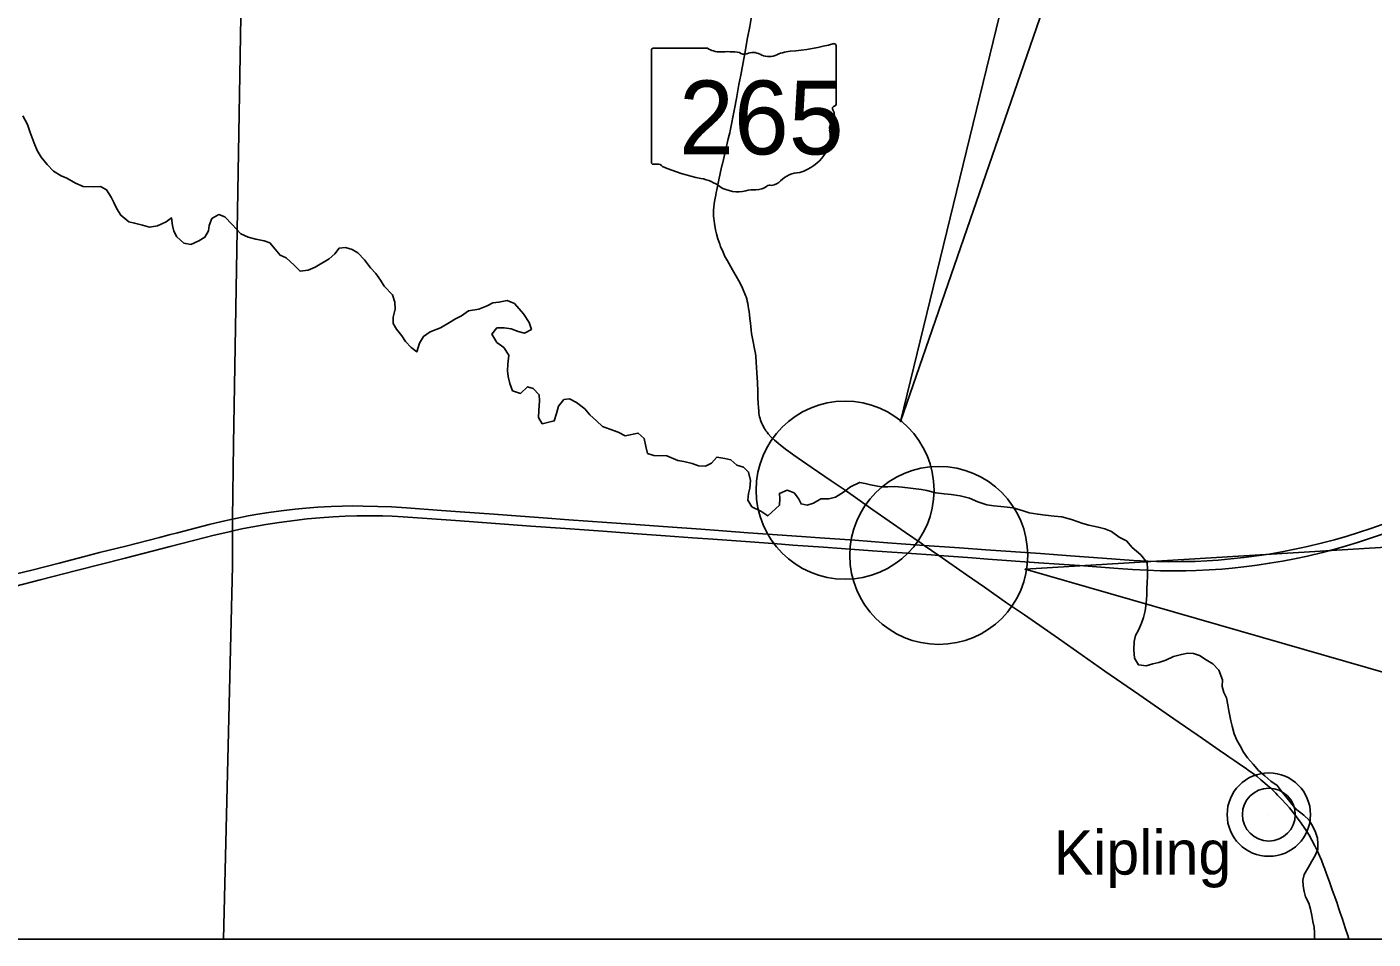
# Model space of a CAD drawing. Extents: x -29.6 to 34, y 0 to 22.
# Drawn here: x -22.122 to -19.868, y 1.053 to 2.58 of the extents above; entities that cross this region are included whole.
import ezdxf

# ---------------------------------------------------------------- set-up
doc = ezdxf.new("R2010")
doc.units = 0
for name, color, linetype in [('BR_P_Gen_Text', 7, 'Continuous'), ('Default', 7, 'Continuous'), ('GM_X_Interstate_Route', 7, 'Continuous'), ('GM_X_Minor_River', 7, 'Continuous'), ('GM_X_State_Route', 7, 'Continuous'), ('GM_X_State_Shield', 7, 'Continuous'), ('GM_X_Township', 7, 'Continuous'), ('GM_X_Township_Road', 7, 'Continuous'), ('GM_X_Unincorporated', 7, 'Continuous'), ('GM_X_Unincorporated_Location', 7, 'Continuous'), ('GM_X_Unincorporated_Text', 7, 'Continuous'), ('SH_Text', 7, 'Continuous')]:
    doc.layers.add(name, color=color, linetype=linetype)

msp = doc.modelspace()

# ---------------------------------------------------------------- linework, layer by layer
at = {"layer": 'BR_P_Gen_Text'}
for points in [[(-20.4101, 2.9402), (-20.4101, 2.64), (-20.6591, 1.919)], [(-19.5899, 1.7242), (-19.5899, 1.424), (-20.4505, 1.6719)]]:
    msp.add_lwpolyline(points, close=True, dxfattribs=at)
at = {"layer": 'Default'}
for centre in [(-20.7519, 1.8042), (-20.595, 1.6949)]:
    msp.add_circle(centre, 0.149, dxfattribs=at)
at = {"layer": 'GM_X_Interstate_Route'}
for points in [[(-22.1427, 1.6431), (-22.0993, 1.6543), (-22.0389, 1.6697), (-21.9571, 1.6904), (-21.8821, 1.7096), (-21.8426, 1.7197), (-21.8082, 1.7286), (-21.7804, 1.7352), (-21.777, 1.736), (-21.7593, 1.7398), (-21.7433, 1.743), (-21.7215, 1.7468), (-21.6991, 1.7503), (-21.6736, 1.7536), (-21.6522, 1.756), (-21.6313, 1.7579), (-21.6092, 1.7595), (-21.5889, 1.7605), (-21.5691, 1.7611), (-21.5475, 1.7613), (-21.5265, 1.761), (-21.5102, 1.7604), (-21.4916, 1.7594), (-21.412, 1.7538), (-21.3964, 1.7526)], [(-22.139, 1.6641), (-22.1136, 1.6705), (-22.0679, 1.6822), (-22.025, 1.6933), (-22.0002, 1.6996), (-21.9561, 1.7107), (-21.8997, 1.7251), (-21.8834, 1.7294), (-21.8693, 1.733), (-21.8163, 1.7465), (-21.7953, 1.7516), (-21.7773, 1.7556), (-21.772, 1.7568), (-21.751, 1.7612), (-21.7349, 1.7641), (-21.7166, 1.767), (-21.6958, 1.7698), (-21.6727, 1.7724), (-21.6547, 1.7741), (-21.6344, 1.7756), (-21.6123, 1.7768), (-21.5937, 1.7774), (-21.5769, 1.7777), (-21.5588, 1.7775), (-21.5344, 1.7769), (-21.5111, 1.776), (-21.4862, 1.7745), (-21.4275, 1.7703), (-21.3964, 1.768)], [(-21.3964, 1.768), (-21.3398, 1.7638), (-21.2951, 1.7605), (-21.2574, 1.7578), (-21.2144, 1.7547), (-21.151, 1.7502), (-21.1028, 1.7468), (-21.0488, 1.7428), (-20.9936, 1.7387), (-20.964, 1.7366), (-20.914, 1.733), (-20.8251, 1.7266), (-20.7943, 1.7244), (-20.7357, 1.7202), (-20.6811, 1.7161), (-20.6192, 1.7117), (-20.5602, 1.7077), (-20.516, 1.7045), (-20.4248, 1.698), (-20.3743, 1.6941), (-20.3208, 1.6903), (-20.2691, 1.6866), (-20.2452, 1.6853), (-20.2301, 1.6847), (-20.2108, 1.6844), (-20.1893, 1.6845), (-20.166, 1.685), (-20.1462, 1.6859), (-20.127, 1.6872), (-20.106, 1.689), (-20.084, 1.6914), (-20.0632, 1.6941), (-20.0419, 1.6973), (-20.0206, 1.7009), (-19.9989, 1.7052), (-19.9778, 1.7098), (-19.9546, 1.7154), (-19.9325, 1.7211), (-19.9113, 1.7273), (-19.8923, 1.7332), (-19.8719, 1.7401), (-19.8527, 1.7469)], [(-21.3964, 1.7526), (-21.3446, 1.7488), (-21.2778, 1.7441), (-21.2198, 1.7399), (-21.1576, 1.7354), (-21.0995, 1.7313), (-21.0524, 1.7278), (-21.0071, 1.7246), (-20.9734, 1.7221), (-20.9031, 1.717), (-20.8584, 1.7136), (-20.8392, 1.7122), (-20.7881, 1.7085), (-20.7585, 1.7064), (-20.7062, 1.7028), (-20.6895, 1.7015)], [(-20.1811, 1.6693), (-20.164, 1.6697), (-20.1425, 1.6708), (-20.121, 1.6722), (-20.1036, 1.6737), (-20.0845, 1.6757), (-20.062, 1.6786), (-20.0412, 1.6817), (-20.0194, 1.6854), (-19.9994, 1.6893), (-19.9778, 1.6939), (-19.9524, 1.7001), (-19.9298, 1.7059), (-19.9125, 1.7109), (-19.8941, 1.7164), (-19.8736, 1.7232), (-19.8522, 1.7307)], [(-20.6895, 1.7015), (-20.6736, 1.7004), (-20.6472, 1.6985)], [(-20.6472, 1.6985), (-20.6405, 1.698), (-20.608, 1.6958), (-20.595, 1.6949), (-20.5702, 1.6931), (-20.5391, 1.6908)], [(-20.5391, 1.6908), (-20.5127, 1.6888), (-20.4273, 1.6826), (-20.3593, 1.6778), (-20.3239, 1.6752), (-20.2948, 1.6731)], [(-20.2948, 1.6731), (-20.2704, 1.6714), (-20.2466, 1.6701), (-20.2239, 1.6693), (-20.2035, 1.6691), (-20.182, 1.6693), (-20.1811, 1.6693)]]:
    msp.add_lwpolyline(points, dxfattribs=at)
at = {"layer": 'GM_X_Minor_River'}
for points in [[(-22.1287, 2.4309), (-22.1208, 2.4164), (-22.1161, 2.4026), (-22.1096, 2.3849), (-22.1046, 2.3725), (-22.0978, 2.3618), (-22.0878, 2.3495), (-22.0771, 2.3382), (-22.0643, 2.3301), (-22.055, 2.3263), (-22.0404, 2.3179), (-22.0276, 2.3123), (-22.0106, 2.3117), (-21.9982, 2.3125), (-21.9883, 2.3069), (-21.9804, 2.2948)], [(-21.9804, 2.2948), (-21.9764, 2.2856), (-21.9711, 2.275), (-21.9646, 2.2644), (-21.9511, 2.2531), (-21.9415, 2.2511), (-21.928, 2.248), (-21.9166, 2.2445), (-21.9028, 2.2467), (-21.8887, 2.2536), (-21.8795, 2.26), (-21.8777, 2.2473), (-21.8755, 2.2377), (-21.8708, 2.2281), (-21.8587, 2.2176), (-21.8474, 2.2155), (-21.8336, 2.2213), (-21.8237, 2.2274), (-21.8177, 2.2381), (-21.8164, 2.247), (-21.8122, 2.2587), (-21.8002, 2.2656), (-21.7903, 2.2617), (-21.7781, 2.2487), (-21.7635, 2.2332), (-21.7511, 2.2279), (-21.7386, 2.2245), (-21.7244, 2.2217), (-21.7152, 2.2182), (-21.7063, 2.2073), (-21.6977, 2.1974), (-21.6874, 2.1929), (-21.6742, 2.1809), (-21.6642, 2.1706), (-21.6508, 2.1725), (-21.6388, 2.1772), (-21.6158, 2.1912), (-21.6063, 2.1998), (-21.5989, 2.2091), (-21.588, 2.2103), (-21.5773, 2.2071), (-21.5677, 2.2012), (-21.5566, 2.1899), (-21.5463, 2.1765), (-21.5373, 2.1666), (-21.5298, 2.1556), (-21.5234, 2.1454), (-21.5098, 2.1309), (-21.5058, 2.1188), (-21.5054, 2.1071), (-21.5085, 2.0936), (-21.5084, 2.0833), (-21.5031, 2.0737), (-21.4941, 2.0624), (-21.488, 2.0533), (-21.4781, 2.0427), (-21.4688, 2.036), (-21.4643, 2.0502), (-21.4576, 2.0616), (-21.4467, 2.0692), (-21.4294, 2.076), (-21.4139, 2.085), (-21.404, 2.0911), (-21.3964, 2.095)], [(-21.3964, 2.095), (-21.3941, 2.0962), (-21.3821, 2.1044), (-21.3648, 2.1074), (-21.351, 2.1128), (-21.3418, 2.1175), (-21.3315, 2.1187), (-21.3174, 2.1216), (-21.3056, 2.1164), (-21.2903, 2.0994), (-21.2806, 2.0849), (-21.277, 2.0732), (-21.2887, 2.0671), (-21.299, 2.0695), (-21.3107, 2.0744), (-21.3224, 2.0757), (-21.3348, 2.076), (-21.3432, 2.0653), (-21.335, 2.0515), (-21.3232, 2.0431), (-21.3146, 2.0303), (-21.3163, 2.015), (-21.3169, 2.004), (-21.3162, 1.9944), (-21.3132, 1.9827), (-21.3086, 1.9707), (-21.2951, 1.9662), (-21.2838, 1.9773), (-21.2739, 1.9741), (-21.2642, 1.9639), (-21.2635, 1.9536), (-21.2644, 1.9373), (-21.2654, 1.9259), (-21.2589, 1.9153), (-21.2388, 1.92), (-21.235, 1.9325), (-21.2315, 1.9446), (-21.2227, 1.956), (-21.2135, 1.9572)], [(-21.2135, 1.9572), (-21.2018, 1.9509), (-21.1875, 1.9403), (-21.1793, 1.9304), (-21.1679, 1.9202), (-21.1579, 1.911), (-21.1455, 1.9061), (-21.1316, 1.9013), (-21.1199, 1.8953), (-21.0983, 1.8997), (-21.0884, 1.8909), (-21.0854, 1.8771), (-21.0825, 1.8657), (-21.0722, 1.8623), (-21.0502, 1.8614), (-21.0318, 1.854), (-21.0218, 1.852), (-21.008, 1.8489), (-20.997, 1.8447), (-20.9853, 1.8444), (-20.9754, 1.8491), (-20.9663, 1.8595), (-20.9531, 1.8571), (-20.9432, 1.8547), (-20.9332, 1.8462), (-20.9222, 1.8424), (-20.9133, 1.8343), (-20.9104, 1.8204), (-20.9113, 1.8076), (-20.9134, 1.7984), (-20.9144, 1.7874), (-20.9079, 1.7764), (-20.8927, 1.769), (-20.8813, 1.761), (-20.8619, 1.7792), (-20.8609, 1.7895), (-20.8617, 1.7987), (-20.849, 1.8042), (-20.8372, 1.7996), (-20.8301, 1.7904), (-20.8254, 1.7812), (-20.8151, 1.7788), (-20.8045, 1.7825), (-20.7925, 1.7896), (-20.7791, 1.7894), (-20.7677, 1.7927), (-20.7547, 1.8009), (-20.7427, 1.8099), (-20.7275, 1.8171), (-20.7183, 1.8154), (-20.7091, 1.8133), (-20.6913, 1.8096), (-20.6803, 1.8096), (-20.6687, 1.8101), (-20.6563, 1.8094), (-20.624, 1.8051), (-20.6148, 1.8037), (-20.5999, 1.7999), (-20.586, 1.7979), (-20.5743, 1.7969), (-20.5594, 1.7945), (-20.5435, 1.7907), (-20.5296, 1.7848), (-20.5143, 1.7795), (-20.503, 1.7779), (-20.4913, 1.7769), (-20.4806, 1.7759), (-20.4704, 1.7745), (-20.4537, 1.7693), (-20.4434, 1.7662), (-20.4292, 1.7638), (-20.4161, 1.7625), (-20.4019, 1.7608), (-20.3891, 1.7598), (-20.3728, 1.7553), (-20.354, 1.7484), (-20.344, 1.7456), (-20.3281, 1.7425), (-20.3171, 1.7394), (-20.306, 1.7348), (-20.2932, 1.7257), (-20.2808, 1.7194), (-20.2711, 1.7081), (-20.2565, 1.6958), (-20.2462, 1.6823), (-20.2454, 1.6724), (-20.2457, 1.66), (-20.2459, 1.6493), (-20.2469, 1.6397), (-20.2465, 1.6284), (-20.2475, 1.6148), (-20.2495, 1.602), (-20.2523, 1.591), (-20.2558, 1.5814), (-20.2606, 1.57), (-20.2659, 1.5607), (-20.2676, 1.5508), (-20.2682, 1.5369), (-20.2676, 1.5367)], [(-20.1202, 1.4868), (-20.1263, 1.5031), (-20.1363, 1.5133), (-20.1473, 1.52), (-20.1587, 1.5274), (-20.1683, 1.5305), (-20.1778, 1.5312), (-20.1888, 1.5293), (-20.2022, 1.5257), (-20.215, 1.5195), (-20.2263, 1.5159), (-20.2365, 1.5133), (-20.2475, 1.5101), (-20.2606, 1.5117), (-20.2674, 1.5231), (-20.2682, 1.5369)], [(-20.1202, 1.4868), (-20.1204, 1.4758), (-20.1175, 1.4656), (-20.1135, 1.4564), (-20.1113, 1.445), (-20.1091, 1.4348), (-20.1058, 1.4181), (-20.1036, 1.4089), (-20.1003, 1.3965), (-20.0959, 1.3855), (-20.0905, 1.376), (-20.0848, 1.3657), (-20.0779, 1.3559), (-20.0686, 1.3453), (-20.0597, 1.3348), (-20.049, 1.326), (-20.039, 1.3172), (-20.0283, 1.3099), (-20.02, 1.2986), (-20.0118, 1.2884), (-20.0036, 1.2778), (-19.9964, 1.2694)], [(-19.964, 1.2315), (-19.9687, 1.2414), (-19.9748, 1.2519), (-19.9838, 1.2604), (-19.9982, 1.2715)], [(-19.9657, 1.0528), (-19.9658, 1.063), (-19.9666, 1.0729), (-19.9688, 1.0821), (-19.9703, 1.0924), (-19.9726, 1.1027), (-19.9755, 1.113), (-19.9809, 1.1232), (-19.9835, 1.1324), (-19.985, 1.142), (-19.9855, 1.1516), (-19.9831, 1.1609), (-19.9758, 1.173), (-19.9702, 1.1831), (-19.9646, 1.1924), (-19.9605, 1.2031), (-19.9606, 1.212), (-19.961, 1.2219), (-19.964, 1.2315)]]:
    msp.add_lwpolyline(points, dxfattribs=at)
at = {"layer": 'GM_X_State_Route'}
for points in [[(-20.8883, 2.7537), (-20.8887, 2.7494), (-20.8895, 2.7388), (-20.89, 2.7321), (-20.8904, 2.7269), (-20.8915, 2.7193), (-20.8929, 2.709), (-20.8967, 2.6795), (-20.9023, 2.6392), (-20.9064, 2.6103), (-20.9089, 2.5937), (-20.9112, 2.5805), (-20.915, 2.5611), (-20.9198, 2.5353), (-20.9255, 2.5048)], [(-20.9255, 2.5048), (-20.9266, 2.4986), (-20.9296, 2.4832), (-20.9338, 2.4597), (-20.937, 2.4425), (-20.9443, 2.4055), (-20.945, 2.4021), (-20.9459, 2.3982), (-20.9474, 2.3921), (-20.9514, 2.3746), (-20.9577, 2.3483)], [(-20.9577, 2.3483), (-20.9581, 2.347), (-20.9605, 2.3368), (-20.9639, 2.3209), (-20.9668, 2.3067), (-20.9675, 2.3027), (-20.9684, 2.2981), (-20.9694, 2.2929), (-20.9704, 2.2872), (-20.9711, 2.2832), (-20.9718, 2.278), (-20.9723, 2.2727), (-20.9724, 2.2701), (-20.9724, 2.2674), (-20.9723, 2.2652), (-20.9723, 2.2633), (-20.9718, 2.2586), (-20.9713, 2.2549), (-20.9706, 2.2505), (-20.9688, 2.2402), (-20.9672, 2.2333), (-20.9647, 2.2249), (-20.9618, 2.216), (-20.9602, 2.2116), (-20.9584, 2.2073), (-20.9562, 2.2023), (-20.9535, 2.1966), (-20.9489, 2.1879), (-20.9406, 2.1731), (-20.93, 2.1544), (-20.925, 2.1452), (-20.9223, 2.1394), (-20.9196, 2.133), (-20.9185, 2.1302), (-20.9176, 2.1276), (-20.9166, 2.1242), (-20.9157, 2.1205), (-20.9148, 2.1168), (-20.9141, 2.1128), (-20.9133, 2.1085), (-20.9125, 2.1033), (-20.9118, 2.0975), (-20.9112, 2.0917), (-20.9104, 2.0836), (-20.9098, 2.0781), (-20.9091, 2.0721), (-20.9084, 2.0664), (-20.9075, 2.0611), (-20.9051, 2.0498), (-20.9038, 2.0436), (-20.9028, 2.0382), (-20.902, 2.0331), (-20.9014, 2.0281), (-20.9006, 2.0183), (-20.8995, 2.0003), (-20.8987, 1.9846), (-20.8981, 1.9695), (-20.8977, 1.9585), (-20.8973, 1.9492), (-20.897, 1.9427), (-20.8964, 1.9363), (-20.8961, 1.9331), (-20.8955, 1.9299), (-20.8949, 1.9271), (-20.8941, 1.9242), (-20.8933, 1.9214), (-20.8923, 1.9186), (-20.8911, 1.916), (-20.89, 1.9133), (-20.8887, 1.9106), (-20.8872, 1.9081), (-20.8859, 1.9058), (-20.8843, 1.9034), (-20.8825, 1.901), (-20.8805, 1.8985), (-20.8762, 1.8937), (-20.8698, 1.8876), (-20.8641, 1.8826), (-20.86, 1.8793), (-20.8549, 1.8754), (-20.8517, 1.8729), (-20.8461, 1.8687), (-20.8379, 1.863), (-20.8232, 1.8527), (-20.8067, 1.8416), (-20.7749, 1.82), (-20.7519, 1.8042), (-20.7052, 1.7715), (-20.6506, 1.7335), (-20.6246, 1.7154)], [(-20.6246, 1.7154), (-20.6192, 1.7117), (-20.595, 1.6949), (-20.5483, 1.6624), (-20.5187, 1.6417), (-20.4814, 1.6157), (-20.4517, 1.5953), (-20.3947, 1.5557), (-20.355, 1.5281), (-20.3169, 1.5014), (-20.2603, 1.4624), (-20.2014, 1.4215), (-20.1534, 1.3885), (-20.1255, 1.3691), (-20.1131, 1.3606), (-20.1094, 1.358), (-20.0991, 1.3509), (-20.0938, 1.3473), (-20.0799, 1.3376), (-20.0771, 1.3356), (-20.0681, 1.3291), (-20.062, 1.3246), (-20.0556, 1.3195), (-20.0489, 1.3139), (-20.0446, 1.31), (-20.0393, 1.3054), (-20.0305, 1.2968), (-20.0277, 1.2939), (-20.0216, 1.2876), (-20.0129, 1.2782), (-20.0079, 1.2725), (-20.0016, 1.2648), (-19.9959, 1.2574), (-19.9883, 1.247), (-19.9831, 1.2393), (-19.979, 1.2329), (-19.9751, 1.2264), (-19.9705, 1.2183), (-19.9656, 1.209), (-19.9617, 1.2011), (-19.9592, 1.1958), (-19.9545, 1.1846), (-19.9509, 1.1753), (-19.9494, 1.1715), (-19.9458, 1.1617), (-19.9404, 1.1469), (-19.9363, 1.1354), (-19.9329, 1.1261), (-19.9288, 1.1145), (-19.9251, 1.1035), (-19.9229, 1.0969), (-19.9197, 1.0875), (-19.9138, 1.0698), (-19.9101, 1.0588), (-19.9082, 1.0528)]]:
    msp.add_lwpolyline(points, dxfattribs=at)
at = {"layer": 'GM_X_State_Shield'}
for p, q in [((-20.767, 2.4503), (-20.767, 2.5484)), ((-21.076, 2.5406), (-21.076, 2.3529)), ((-20.9824, 2.5438), (-21.0729, 2.5438)), ((-20.767, 2.4503), (-20.767, 2.4503))]:
    msp.add_line(p, q, dxfattribs=at)
for centre, major_axis, start_param, end_param in [((-20.877, 2.7996), (0.3277, 0), 4.814394, 5.042369), ((-20.7704, 2.5488), (0.00344, 0), 6.141152, 7.989035), ((-21.0724, 2.541), (0.00358, 0), 1.712693, 3.28349), ((-20.9609, 2.5656), (0.0347, 0), 4.042523, 4.731795), ((-20.9494, 2.4385), (0.1246, 0), 1.404758, 1.657858), ((-20.9211, 2.5419), (0.01, 0), 3.836095, 5.185415), ((-20.9064, 2.5202), (0.0208, 0), 0.950623, 2.079405), ((-20.8795, 2.55), (0.0251, 0), 4.081561, 5.145723), ((-20.8352, 2.4865), (0.0659, 0), 1.699011, 2.107814), ((-20.7678, 2.4431), (0.00532, 0), 1.883978, 3.671073), ((-20.8016, 2.4307), (0.032, 0), 5.934695, 6.695948), ((-20.7706, 2.4499), (0.00368, 0), 5.05454, 6.418171), ((-20.7546, 2.4092), (0.0232, 0), 2.387724, 3.262537), ((-20.8587, 2.3967), (0.082, 0), 5.101752, 6.440018), ((-21.0724, 2.3525), (0.00361, 0), 3.00124, 4.508301), ((-21.0718, 2.3717), (0.0276, 0), 4.665946, 4.897461), ((-21.0662, 2.3421), (0.00994, 0), 0.519207, 1.627899), ((-20.9407, 2.5107), (0.2366, 0), 4.195997, 4.488961), ((-21.0113, 2.2687), (0.074, 0), 0.823519, 1.323587), ((-20.881, 2.3348), (0.0265, 0), 4.937069, 5.64225), ((-20.8241, 2.3003), (0.0449, 0), 1.647645, 2.488434), ((-20.9312, 2.3412), (0.047, 0), 4.026481, 4.996735), ((-20.9041, 2.2763), (0.0386, 0), 1.495662, 1.94098), ((-20.9006, 2.3271), (0.025, 0), 4.691044, 5.507374), ((-20.878, 2.309), (0.00705, 0), 1.147584, 2.315152)]:
    msp.add_ellipse(centre, major_axis=major_axis, ratio=0.8, start_param=start_param, end_param=end_param, dxfattribs=at)
at = {"layer": 'GM_X_Township'}
msp.add_lwpolyline([(-21.7629, 2.6297), (-21.776, 1.881), (-21.7775, 1.7561), (-21.7772, 1.7365), (-21.7773, 1.6767), (-21.7923, 1.0528)], dxfattribs=at)
at = {"layer": 'GM_X_Township_Road'}
msp.add_lwpolyline([(-20.9577, 2.3483), (-20.9514, 2.3746), (-20.9474, 2.3921), (-20.9459, 2.3982), (-20.945, 2.4021), (-20.9443, 2.4055), (-20.937, 2.4425), (-20.9338, 2.4597), (-20.9296, 2.4832), (-20.9266, 2.4986), (-20.9255, 2.5048)], dxfattribs=at)
at = {"layer": 'GM_X_Unincorporated'}
for radius in [0.0698, 0.0442]:
    msp.add_circle((-20.0424, 1.2611), radius, dxfattribs=at)
at = {"layer": 'GM_X_Unincorporated_Location'}
msp.add_line((-20.0424, 1.2611), (-20.0424, 1.2611), dxfattribs=at)
at = {"layer": 'SH_Text'}
msp.add_lwpolyline([(-29.5833, 13.2079), (-10.7478, 13.2079), (-10.7478, 1.0528), (-29.5833, 1.0528)], close=True, dxfattribs=at)

# ---------------------------------------------------------------- texts
at = {"layer": 'GM_X_State_Shield'}
msp.add_text('265', height=0.1236, dxfattribs=at).set_placement((-21.0299, 2.3662))
at = {"layer": 'GM_X_Unincorporated_Text'}
msp.add_text('Kipling', height=0.07404, rotation=0, dxfattribs=at).set_placement((-20.4025, 1.1607))

doc.saveas('drawing.dxf')
